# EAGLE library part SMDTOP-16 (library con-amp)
AMP connector
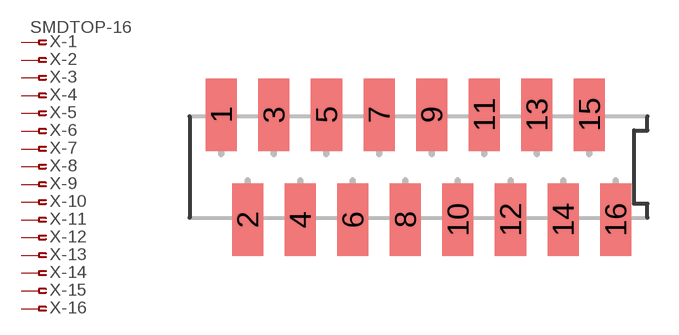
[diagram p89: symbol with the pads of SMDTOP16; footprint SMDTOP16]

Designator prefix X; gates -1=PIN-FV -2=PIN-F -3=PIN-F -4=PIN-F -5=PIN-F -6=PIN-F -7=PIN-F -8=PIN-F -9=PIN-F -10=PIN-F -11=PIN-F -12=PIN-F -13=PIN-F -14=PIN-F -15=PIN-F -16=PIN-F

## SMDTOP-16 (OC_FARNELL: unknown; OC_NEWARK: unknown)  [SMDTOP16]
1  -1:1  pas
2  -2:1  pas
3  -3:1  pas
4  -4:1  pas
5  -5:1  pas
6  -6:1  pas
7  -7:1  pas
8  -8:1  pas
9  -9:1  pas
10  -10:1  pas
11  -11:1  pas
12  -12:1  pas
13  -13:1  pas
14  -14:1  pas
15  -15:1  pas
16  -16:1  pas

## Footprint SMDTOP16 (pad centres in mm)
AMP connector
smd 1.5 x 3.5: 1 -9.525,2.54; 2 -8.255,-2.54; 3 -6.985,2.54; 4 -5.715,-2.54; 5 -4.445,2.54; 6 -3.175,-2.54; 7 -1.905,2.54; 8 -0.635,-2.54; 9 0.635,2.54; 10 1.905,-2.54; 11 3.175,2.54; 12 4.445,-2.54; 13 5.715,2.54; 14 6.985,-2.54; 15 8.255,2.54; 16 9.525,-2.54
